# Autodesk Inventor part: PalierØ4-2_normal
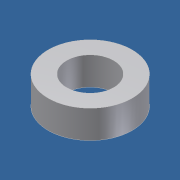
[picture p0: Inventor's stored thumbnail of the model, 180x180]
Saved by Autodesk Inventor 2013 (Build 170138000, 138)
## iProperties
Created: 2011-07
Part Number: PalierØ4-2_normal
Document SubType Name: Modeling
Designer: domi
Density: 1 g/cm^3
Material: Générique
Author: domi
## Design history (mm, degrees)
sketch "Esquisse1"
  geometry: C1 r 2.1 at (0, 0); C2 r 3.75 at (0, 0); 1 further point
  constraints: 2 centre point, 2 coincident
  dimensions: "d0" = 7.5 diameter of C2; "d1" = 4.2 diameter of C1
extrude "Pallier" new body sketch "Esquisse1" distance "d2" = 2.5; taper "d3" = 0 deg
node "Solide1"
node "Corps solides"
node "Corps surfaciques"
